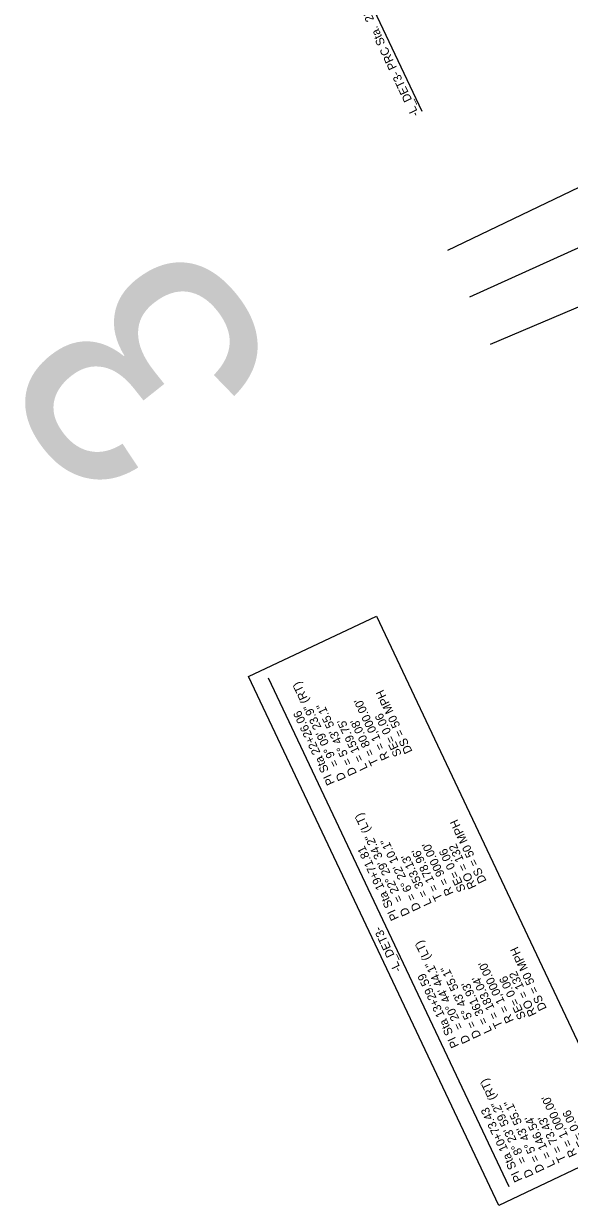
# Model space of a CAD drawing. Extents: x 473658 to 481584, y 489119 to 506230.
# Drawn here: x 477084 to 477538, y 498591 to 499575 of the extents above; entities that cross this region are included whole.
import ezdxf

# ---------------------------------------------------------------- set-up
doc = ezdxf.new("R2010")
doc.units = 0
for name, color, linetype in [('Prop Grid Mask', 7, 'Continuous'), ('Prop Horizontal Alignment Curve and Spiral Data', 7, 'Continuous'), ('Prop Horizontal Alignment Station Label', 7, 'Continuous'), ('Scratch_Level_5', 7, 'Continuous'), ('Sheet Block Title CELL', 7, 'Continuous')]:
    doc.layers.add(name, color=color, linetype=linetype)

msp = doc.modelspace()

# ---------------------------------------------------------------- linework, layer by layer
at = {"layer": 'Prop Grid Mask'}
msp.add_lwpolyline([(477479.37, 498590.75), (477271.19, 499031.28), (477377.66, 499081.6), (477585.84, 498641.07)], close=True, dxfattribs=at)
at = {"layer": 'Prop Horizontal Alignment Station Label'}
for p, q in [((477415.69, 499501.9), (477354.44, 499631.5)), ((477488.04, 498606.09), (477287.82, 499029.79))]:
    msp.add_line(p, q, dxfattribs=at)
at = {"layer": 'Scratch_Level_5'}
for p, q in [((477437.03, 499386.41), (477812.95, 499567.27)), ((477455.19, 499347.5), (477835.26, 499519.46)), ((477472.43, 499308.17), (477856.44, 499471.15))]:
    msp.add_line(p, q, dxfattribs=at)

# ---------------------------------------------------------------- texts
at = {"layer": 'Prop Horizontal Alignment Curve and Spiral Data'}
for s, p in [('= 9%%d 09\' 23.9" (RT)', (477346.66, 498957.84)), ('DS = 50 MPH', (477407.69, 498968.93)), ('D = 5%%d 43\' 55.1"', (477361.45, 498950.62)), ("R = 1,000.00'", (477388.58, 498963.43)), ('PI Sta 22+26.06', (477343.08, 498942.68)), ('SE= 0.06', (477398.83, 498966.43)), ("L = 159.75'", (477370.5, 498954.89)), ("T = 80.08'", (477379.54, 498959.16)), ('D', (477352.41, 498946.34)), ('= 22%%d 29\' 34.2" (LT)', (477399.96, 498845.1)), ('DS = 50 MPH', (477469.38, 498860.98)), ('PI Sta 19+71.81', (477396.39, 498829.95)), ('D = 6%%d 22\' 10.1"', (477414.76, 498837.88)), ("R = 900.00'", (477441.89, 498850.7)), ('SE= 0.06', (477452.14, 498853.7)), ('RO = 132', (477461, 498856.2)), ("L = 353.13'", (477423.8, 498842.15)), ("T = 178.96'", (477432.84, 498846.43)), ('D', (477405.72, 498833.61)), ('= 20%%d 44\' 44.1" (LT)', (477450.11, 498738.97)), ('DS = 50 MPH', (477519.52, 498754.85)), ("R = 1,000.00'", (477492.03, 498744.57)), ('PI Sta 13+29.59', (477446.53, 498723.81)), ('D = 5%%d 43\' 55.1"', (477464.9, 498731.75)), ("T = 183.04'", (477482.99, 498740.29)), ('SE= 0.06', (477502.28, 498747.56)), ('RO = 132', (477511.14, 498750.07)), ("L = 361.93'", (477473.94, 498736.02)), ('D', (477455.86, 498727.48)), ('= 8%%d 23\' 59.2" (RT)', (477502.81, 498627.29)), ("R = 1,000.00'", (477544.73, 498632.88)), ('PI Sta 10+73.43', (477499.24, 498612.13)), ('D = 5%%d 43\' 55.1"', (477517.61, 498620.07)), ("L = 146.54'", (477526.65, 498624.34)), ("T = 73.43'", (477535.69, 498628.61)), ('SE= 0.06', (477554.99, 498635.88)), ('D', (477508.57, 498615.79))]:
    msp.add_text(s, height=7, rotation=115.2938, dxfattribs=at).set_placement(p)
at = {"layer": 'Prop Horizontal Alignment Station Label'}
for s, p in [('-L_DET3- PRC Sta.  21+45.99', (477413.15, 499499.51)), ('-L_DET3-', (477398.58, 498786.96))]:
    msp.add_text(s, height=7, rotation=115.2938, dxfattribs=at).set_placement(p)
at = {"layer": 'Sheet Block Title CELL'}
msp.add_text('3', height=200, rotation=128.44881, dxfattribs=at).set_placement((477305.82, 499288.85))

doc.saveas('drawing.dxf')
